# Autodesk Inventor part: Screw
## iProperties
Created: 2002-01
Part Number: Screw
Document SubType Name: Modeling
Designer: ***
Control State: 0
Master: False
Checked Out: False
Shininess: 20.0
Length Units: 11269
Angle Units: 11279
Time Units: 11290
Mass Units: 11283
Length Display Precision: 3
Angle Display Precision: 2
Density: 0.0
Volumn: 0.0
Area: 0.0
PropertySet Name: Model Information
Author: ***
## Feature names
1. Revolution1
2. Extrusion2
3. Extrusion3
4. Chamfer1
